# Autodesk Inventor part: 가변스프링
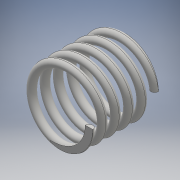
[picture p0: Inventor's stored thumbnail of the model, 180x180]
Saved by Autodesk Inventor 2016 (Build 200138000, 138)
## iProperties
Created: 2019-11
Part Number: 가변스프링
Material: 일반
Document SubType Name: Modeling
Designer: user
Density: 1 g/cm^3
Appearance: 기본값
Mass: 0.819704 g
Surface Area: 16.7052 cm^2
Volume: 0.819704 cm^3
Author: user
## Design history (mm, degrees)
sketch "스케치1"
  geometry: L1 (0, 0)-(8.5, 0); L2 (8.5, 0)-(8.5, 17.5); L3 (8.5, 17.5)-(0, 17.5); L4 (0, 17.5)-(0, 0); C1 r 1 at (8.5, 0)
  constraints: 8 end point, 2 parallel, 1 centre point, 1 coincident, 1 horizontal, 1 perpendicular
  dimensions: "d1" = 17 diameter of L2 L4; "d2" = 17.5 distance between parallel lines of L1 L3 (derived); "d3" = 2 diameter of C1
feature "코일1" sketch "스케치1" pitch "d4" = 10; turns "d6" = 5; dims "d5" = 17.5 (= d2), "d7" = 0, angle "d8" = 90 deg, angle "d9" = 90 deg, "d10" = 0, "d11" = 0
sketch "스케치2"
  geometry: L1 (0, 13.879)-(17.5, 13.879); L2 (17.5, 13.879)-(17.5, -13.879); L3 (17.5, -13.879)-(0, -13.879); L4 (0, -13.879)-(0, 13.879); 2 further points
  constraints: 8 end point, 2 parallel, 1 coincident, 1 horizontal, 1 midpoint, 1 perpendicular
  dimensions: "d12" = 17.5 distance between parallel lines of L4 L2 (= d2); "d13" = 27.7574 distance between parallel lines of L1 L3
extrude "돌출1" sketch "스케치2" stored distance "d14" = 50; taper "d15" = 0 deg
node "솔리드1"
